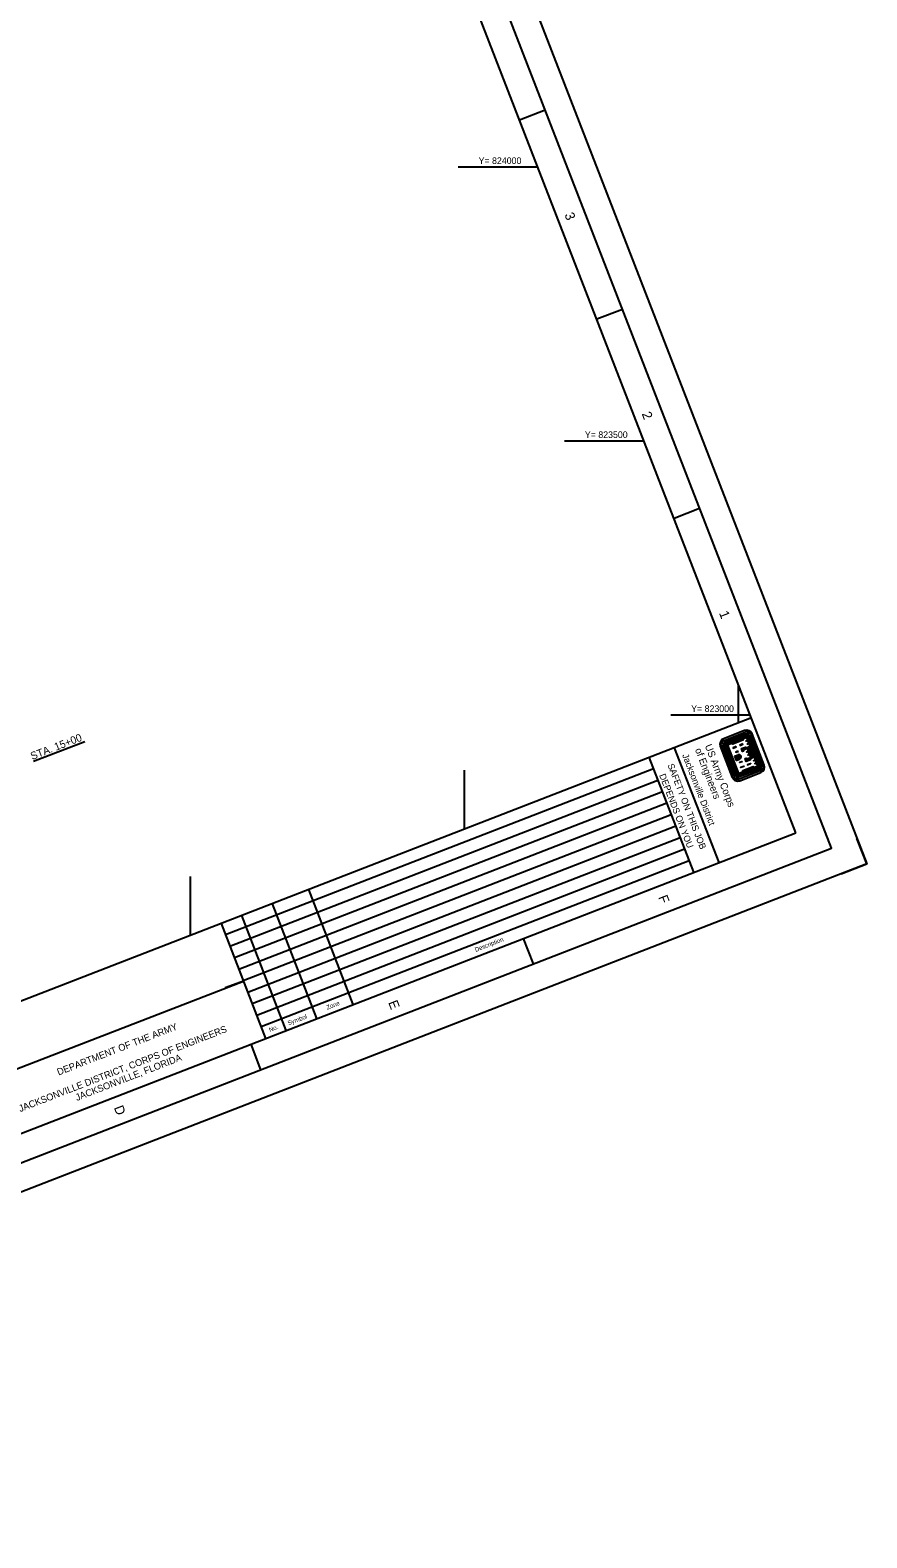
# Model space of a CAD drawing. Extents: x 588973 to 593734, y 821498 to 826830.
# Drawn here: x 592207 to 593734, y 821498 to 824249 of the extents above; entities that cross this region are included whole.
import ezdxf

# ---------------------------------------------------------------- set-up
doc = ezdxf.new("R2010")
doc.units = 0
for name, color, linetype in [('G-ANNO-NPLT', 7, 'Continuous'), ('G-ANNO-TEXT-LOGO', 7, 'Continuous'), ('G-ANNO-TEXT-TTLB', 7, 'Continuous'), ('G-ANNO-TTLB', 7, 'Continuous'), ('V-ALGN-TEXT', 7, 'Continuous'), ('V-TOPO-COOR-STAT', 7, 'Continuous')]:
    doc.layers.add(name, color=color, linetype=linetype)

msp = doc.modelspace()

# ---------------------------------------------------------------- linework, layer by layer
at = {"layer": 'G-ANNO-NPLT'}
msp.add_lwpolyline([(592142.7, 826829.7), (593734.3, 822727.7), (590564.5, 821497.8), (588973, 825599.9)], close=True, dxfattribs=at)
msp.add_lwpolyline([(593687.6, 822709.6), (593734.3, 822727.7), (593716.2, 822774.3)], dxfattribs=at)
at = {"layer": 'G-ANNO-TEXT-LOGO'}
for p, q in [((593511, 822971), (593472.8, 822956.2)), ((593474, 822953.2), (593512.2, 822968)), ((593513.5, 822964.8), (593475.2, 822950)), ((593546.9, 822908.2), (593524.9, 822964.9)), ((593466.6, 822942.3), (593488.6, 822885.6)), ((593491.7, 822886.8), (593469.7, 822943.5)), ((593494.9, 822888.1), (593472.9, 822944.8)), ((593495.7, 822888.4), (593473.7, 822945.1)), ((593496.5, 822888.7), (593474.5, 822945.4)), ((593497.4, 822889), (593475.4, 822945.7)), ((593513.8, 822963.9), (593475.6, 822949.1)), ((593514.1, 822963.2), (593475.8, 822948.4)), ((593498.1, 822889.3), (593476.1, 822946)), ((593514.4, 822962.4), (593476.2, 822947.5)), ((593514.7, 822961.5), (593476.5, 822946.7)), ((593515, 822960.7), (593477.1, 822946)), ((593498.8, 822890), (593477.1, 822946)), ((593515.3, 822959.9), (593478.2, 822945.5)), ((593499.4, 822891.1), (593478.2, 822945.5)), ((593507.5, 822956.1), (593487.9, 822948.5)), ((593507, 822955), (593489.2, 822948.1)), ((593537.5, 822904.6), (593515.5, 822961.3)), ((593538.3, 822904.9), (593516.3, 822961.6)), ((593539, 822905.2), (593517, 822961.9)), ((593517.5, 822939.4), (593524.2, 822922.1)), ((593539.9, 822905.5), (593517.9, 822962.2)), ((593518.3, 822939.8), (593525.1, 822922.4)), ((593540.7, 822905.9), (593518.7, 822962.5)), ((593519.1, 822940), (593525.8, 822922.7)), ((593519.9, 822940.4), (593526.7, 822923)), ((593520.8, 822940.7), (593527.5, 822923.4)), ((593521.5, 822941), (593528.2, 822923.6)), ((593521.9, 822963.8), (593543.9, 822907.1)), ((593522.3, 822941.3), (593529.1, 822924)), ((593492.8, 822924.2), (593499.1, 822926.6)), ((593492.8, 822924.2), (593495.7, 822916.7)), ((593493.1, 822923.4), (593499.4, 822925.9)), ((593493.5, 822922.6), (593499.7, 822925)), ((593493.8, 822921.8), (593500, 822924.2)), ((593494.1, 822921), (593500.3, 822923.4)), ((593494.5, 822919.9), (593500.8, 822922.3)), ((593494.8, 822919.1), (593501, 822921.6)), ((593495.1, 822918.3), (593501.4, 822920.7)), ((593495.4, 822917.5), (593501.7, 822919.9)), ((593495.7, 822916.7), (593502, 822919.1)), ((593536.7, 822904.7), (593498.8, 822890)), ((593537.1, 822903.9), (593498.8, 822889.1)), ((593537.4, 822903.1), (593499.2, 822888.2)), ((593536.5, 822905.5), (593499.4, 822891.1)), ((593537.7, 822902.3), (593499.5, 822887.5)), ((593538, 822901.5), (593499.8, 822886.6)), ((593538.3, 822900.6), (593500.1, 822885.8)), ((593539.6, 822897.5), (593501.3, 822882.6)), ((593502.5, 822879.6), (593540.8, 822894.4)), ((593528, 822903), (593508.6, 822895.4)), ((593526.9, 822903.5), (593509.1, 822896.6))]:
    msp.add_line(p, q, dxfattribs=at)
for points in [[(593515.6, 822959.3), (593508.2, 822956.4), (593507.3, 822954.2), (593489.4, 822947.3), (593487.2, 822948.2), (593479, 822945.1), (593499.7, 822892), (593507.8, 822895.1), (593508.8, 822897.4), (593526.6, 822904.3), (593528.8, 822903.3), (593536.2, 822906.1), (593533.5, 822913.1), (593531.4, 822918.5), (593529.4, 822923.6), (593522.1, 822920.7), (593521.2, 822918.3), (593514.7, 822915.8), (593513.1, 822919.7), (593513.8, 822920), (593516.1, 822918.9), (593523.4, 822921.8), (593520.7, 822928.8), (593518.6, 822934.2), (593516.7, 822939.1), (593509.4, 822936.3), (593508.4, 822934), (593507.7, 822933.7), (593506.2, 822937.6), (593512.7, 822940.1), (593515, 822939.1), (593522.3, 822941.9), (593519.6, 822948.9), (593517.5, 822954.3), (593515.6, 822959.3)], [(593515, 822958.2), (593508.9, 822955.8), (593507.9, 822953.5), (593489.4, 822946.3), (593487.1, 822947.4), (593480.2, 822944.7), (593500.2, 822893), (593507.1, 822895.7), (593508.1, 822898.1), (593526.6, 822905.3), (593528.9, 822904.2), (593535.1, 822906.6), (593533.1, 822911.6), (593530.2, 822910.5), (593530.1, 822910.9), (593532.9, 822912.1), (593531, 822917), (593528.1, 822915.9), (593528, 822916.3), (593530.9, 822917.4), (593528.9, 822922.4), (593522.8, 822920), (593521.7, 822917.7), (593514.2, 822914.8), (593512.1, 822920.2), (593513.9, 822920.9), (593516.2, 822919.8), (593522.4, 822922.2), (593520.4, 822927.3), (593517.5, 822926.1), (593517.4, 822926.5), (593520.3, 822927.6), (593518.3, 822932.7), (593515.4, 822931.5), (593515.2, 822932), (593518.1, 822933.1), (593516.2, 822938.1), (593510, 822935.7), (593509, 822933.4), (593507.3, 822932.7), (593505.2, 822938.1), (593512.7, 822941), (593515, 822940), (593521.2, 822942.4), (593519.3, 822947.3), (593516.4, 822946.2), (593516.2, 822946.6), (593519.1, 822947.8), (593517.1, 822952.8), (593514.2, 822951.7), (593514.1, 822952.1), (593517, 822953.2), (593515, 822958.2)], [(593495.6, 822941.9), (593490.1, 822939.8), (593490.3, 822939.2), (593495.8, 822941.3), (593495.6, 822941.9)], [(593508, 822946.7), (593502.6, 822944.6), (593502.8, 822944), (593508.2, 822946.1), (593508, 822946.7)], [(593513.3, 822938.9), (593512.7, 822939.2), (593507.4, 822937.1), (593508, 822935.3), (593508.8, 822937), (593513.4, 822938.8)], [(593499, 822933.3), (593495.1, 822931.8), (593495.3, 822931.4), (593499.1, 822932.8), (593499, 822933.3)], [(593506.4, 822914.1), (593502.6, 822912.6), (593502.4, 822913.1), (593506.2, 822914.6), (593506.4, 822914.1)], [(593520.8, 822919.7), (593520.5, 822919), (593515.2, 822917), (593514.5, 822918.6), (593516.2, 822918), (593520.8, 822919.8)], [(593522.1, 822910.4), (593516.7, 822908.3), (593516.5, 822908.8), (593521.9, 822910.9), (593522.1, 822910.4)], [(593509.7, 822905.6), (593504.2, 822903.5), (593504, 822904), (593509.5, 822906.1), (593509.7, 822905.6)]]:
    msp.add_lwpolyline(points, dxfattribs=at)
for centre, major_axis, start_param, end_param in [((593514.9, 822961), (3.88, -9.99), 1.57078, 3.141576), ((593514.9, 822961), (2.71, -6.98), 1.57078, 3.141576), ((593514.9, 822961), (1.45, -3.75), 1.57078, 3.141576), ((593514.9, 822961), (1.14, -2.94), 1.57078, 3.141576), ((593476.7, 822946.2), (-3.88, 9.99), 6.28317, 7.853966), ((593476.7, 822946.2), (-2.71, 6.98), 6.28317, 7.853966), ((593476.7, 822946.2), (-1.45, 3.75), 6.28317, 7.853966), ((593476.7, 822946.2), (-1.14, 2.94), 6.28317, 7.853966), ((593476.7, 822946.2), (-0.83, 2.13), 6.28317, 7.853966), ((593476.7, 822946.2), (-0.51, 1.32), 6.28317, 7.853966), ((593476.7, 822946.2), (-0.197, 0.509), 6.28317, 7.853966), ((593514.9, 822961), (0.83, -2.13), 1.57078, 3.141576), ((593514.9, 822961), (0.51, -1.32), 1.57078, 3.141576), ((593514.9, 822961), (0.197, -0.509), 1.57078, 3.141576), ((593500.7, 822921.3), (-2.01, 5.18), 4.985832, 6.214359), ((593500.7, 822921.3), (-1.69, 4.37), 4.947465, 6.21436), ((593500.7, 822921.3), (-1.38, 3.56), 4.947465, 6.21436), ((593500.7, 822921.3), (-1.07, 2.75), 4.947465, 6.21436), ((593500.7, 822921.3), (-0.75, 1.94), 4.947465, 6.214359), ((593499.6, 822924.1), (0.75, -1.94), 0.068794, 1.335689), ((593499.6, 822924.1), (1.07, -2.75), 0.068794, 1.335689), ((593499.6, 822924.1), (1.38, -3.56), 0.068795, 1.335689), ((593499.6, 822924.1), (1.69, -4.37), 0.068795, 1.335689), ((593499.6, 822924.1), (2.01, -5.18), 0.068795, 1.29842), ((593498.6, 822889.6), (3.88, -9.99), 4.712373, 6.28317), ((593498.6, 822889.6), (-2.71, 6.98), 1.570781, 3.141577), ((593498.6, 822889.6), (1.45, -3.75), 4.712373, 6.28317), ((593498.6, 822889.6), (1.14, -2.94), 4.712373, 6.28317), ((593498.6, 822889.6), (0.83, -2.13), 4.712373, 6.28317), ((593498.6, 822889.6), (0.51, -1.32), 4.712373, 6.28317), ((593498.6, 822889.6), (0.197, -0.509), 4.712373, 6.28317), ((593536.9, 822904.4), (0.197, -0.509), 6.283169, 7.853965), ((593536.9, 822904.4), (0.51, -1.32), 6.283169, 7.853965), ((593536.9, 822904.4), (0.83, -2.13), 6.283169, 7.853965), ((593536.9, 822904.4), (1.14, -2.94), 6.283169, 7.853965), ((593536.9, 822904.4), (1.45, -3.75), 6.283169, 7.853965), ((593536.9, 822904.4), (2.71, -6.98), 6.28317, 7.853966), ((593536.9, 822904.4), (3.88, -9.99), 6.283169, 7.853965)]:
    msp.add_ellipse(centre, major_axis=major_axis, ratio=0.99964, start_param=start_param, end_param=end_param, dxfattribs=at)
at = {"layer": 'G-ANNO-TTLB'}
for p, q in [((593146.9, 824103.3), (593100.3, 824085.2)), ((593288, 823739.7), (593241.3, 823721.7)), ((593429, 823376.1), (593382.4, 823358.1)), ((593523.5, 822994.5), (590540.2, 821837)), ((593382.5, 822939.8), (593463.9, 822730)), ((593336.5, 822922.6), (593417.9, 822712.8)), ((593344.8, 822901.2), (592563.6, 822598.1)), ((593352.9, 822880.2), (592571.7, 822577.2)), ((593361, 822859.3), (592579.9, 822556.2)), ((593369.2, 822838.3), (592588, 822535.2)), ((593377.3, 822817.3), (592596.1, 822514.2)), ((593385.5, 822796.3), (592604.3, 822493.2)), ((593393.6, 822775.4), (592612.4, 822472.3)), ((593401.7, 822754.4), (592620.6, 822451.3)), ((593409.9, 822733.4), (592628.7, 822430.3)), ((592715, 822680.8), (592796.3, 822471)), ((592648.6, 822655), (592730, 822445.3)), ((592555.5, 822618.9), (592636.9, 822409.2)), ((592592.7, 822633.3), (592674, 822423.6)), ((593125.6, 822545.1), (593107.5, 822591.7)), ((591794.6, 822203.7), (592596.2, 822514)), ((592596.2, 822514), (592563.2, 822501.3)), ((592628.4, 822352.2), (592610.3, 822398.8))]:
    msp.add_line(p, q, dxfattribs=at)
for points in [[(589037.7, 825571.4), (590593, 821562.5), (593669.6, 822756.2), (592114.2, 826765)], [(593604.9, 822784.7), (592112.8, 826630.4), (589129.5, 825472.9), (590621.6, 821627.2)]]:
    msp.add_lwpolyline(points, close=True, dxfattribs=at)
at = {"layer": 'V-ALGN-TEXT'}
msp.add_line((592213.4, 822915.2), (592306.7, 822951.4), dxfattribs=at)
at = {"layer": 'V-TOPO-COOR-STAT'}
for p, q in [((592988.6, 824000), (593133.4, 824000)), ((593182.5, 823500), (593327.3, 823500)), ((593500, 822985.4), (593500, 823055)), ((593376.5, 823000), (593521.3, 823000)), ((593000, 822791.4), (593000, 822898.7)), ((592500, 822597.4), (592500, 822704.7))]:
    msp.add_line(p, q, dxfattribs=at)

# ---------------------------------------------------------------- texts
at = {"layer": 'G-ANNO-TEXT-TTLB'}
for s, height, rotation, p in [('of Engineers', 13.086, 291.2052, (593420.2, 822936.2)), ('US Army Corps', 13.086, 291.2052, (593438.3, 822943.2)), ('SAFETY ON THIS JOB', 11.9, 291.2052, (593370.3, 822908.1)), ('Jacksonville District', 11.9, 291.2052, (593396.9, 822926.1)), ('DEPENDS ON YOU', 11.9, 291.2052, (593355, 822889.6)), ('Description', 8, 21.2052, (593020.5, 822567)), ('Zone', 8, 21.2052, (592749.6, 822461.6)), ('Symbol', 8, 21.2052, (592678.9, 822432.9)), ('JACKSONVILLE DISTRICT, CORPS OF ENGINEERS', 12.5, 21.2052, (592189, 822274.7)), ('DEPARTMENT OF THE ARMY', 12.5, 21.2052, (592259, 822341.5)), ('No.', 8, 21.2052, (592644.8, 822420.7)), ('JACKSONVILLE, FLORIDA', 12.5, 21.2052, (592292.5, 822295))]:
    msp.add_text(s, height=height, rotation=rotation, dxfattribs=at).set_placement(p)
at = {"layer": 'G-ANNO-TTLB'}
for s, p in [('3', (593182.1, 823912.7)), ('2', (593323.1, 823549.1)), ('1', (593464.2, 823185.6)), ('F', (593353.1, 822666.9)), ('E', (592860.4, 822474.9)), ('D', (592359.7, 822283))]:
    msp.add_text(s, height=17.5, rotation=291.2052, dxfattribs=at).set_placement(p)
at = {"layer": 'V-ALGN-TEXT'}
msp.add_text('STA. 15+00', height=13.92, rotation=21.2052, dxfattribs=at).set_placement((592210.9, 822917.2))
at = {"layer": 'V-TOPO-COOR-STAT'}
for s, p in [('Y= 824000', (593025.6, 824005)), ('Y= 823500', (593219.6, 823505)), ('Y= 823000', (593413.6, 823005))]:
    msp.add_text(s, height=12, dxfattribs=at).set_placement(p)

doc.saveas('drawing.dxf')
